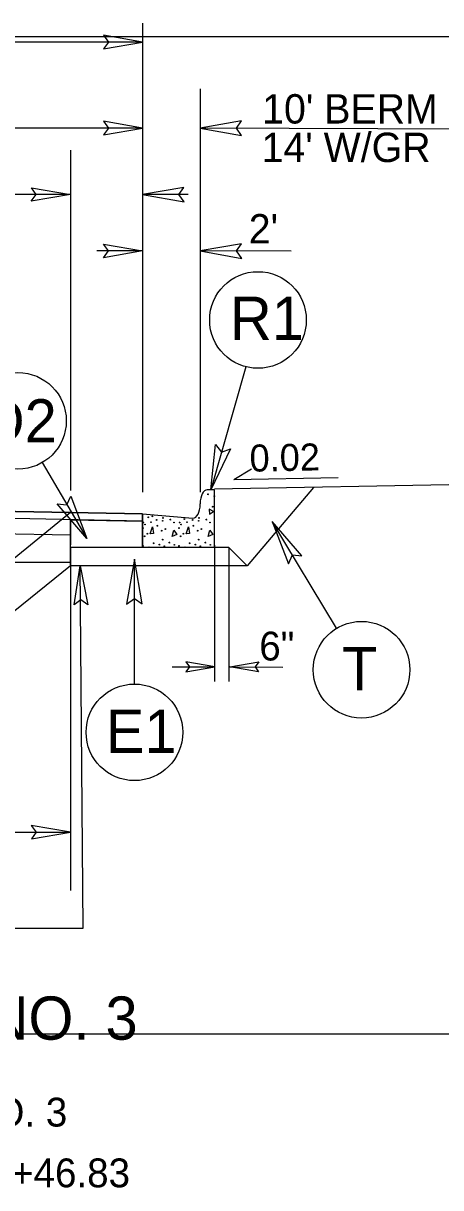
# Model space of a CAD drawing. Extents: x 18938 to 19565, y 6931 to 7973.
# Drawn here: x 19338.35 to 19352.83, y 7710.7 to 7751.1 of the extents above; entities that cross this region are included whole.
import ezdxf

# ---------------------------------------------------------------- set-up
doc = ezdxf.new("R2010")
doc.units = 0
for name, color, linetype in [('Old_Level_11', 7, 'Continuous'), ('Old_Level_3', 7, 'Continuous'), ('Prop Pavement Schedule Description CELL', 7, 'Continuous'), ('Prop Terminator CELL', 7, 'Continuous'), ('Sheet Block Title CELL', 7, 'Continuous'), ('Sheet Cutting Line CELL', 7, 'Continuous'), ('Sheet Data Field CELL', 7, 'Continuous'), ('Sheet Plot Border Inside CELL', 7, 'Continuous'), ('Sheet Sticker Incomplete CELL', 7, 'Continuous'), ('Sheet Typical CELL', 7, 'Continuous'), ('Typical Detail Wedge2 CELL', 7, 'Continuous'), ('Typical Guardrail CELL', 7, 'Continuous'), ('Typical Hinge Slope Arterial CELL', 7, 'Continuous'), ('Typical ID Circle CELL', 7, 'Continuous'), ('Typical Terminator CELL', 7, 'Continuous'), ('Typical Text General CELL', 7, 'Continuous')]:
    doc.layers.add(name, color=color, linetype=linetype)

msp = doc.modelspace()

# ---------------------------------------------------------------- linework, layer by layer
at = {"layer": 'Old_Level_3'}
for p, q in [((19343.507, 7728.771), (19344.983, 7728.771)), ((19345.514, 7728.771), (19347.352, 7728.767))]:
    msp.add_line(p, q, dxfattribs=at)
at = {"layer": 'Prop Pavement Schedule Description CELL'}
for p, q in [((19344.983, 7732.915), (19344.983, 7734.915)), ((19354.484, 7735.112), (19344.986, 7734.934)), ((19348.414, 7734.998), (19346.113, 7732.285)), ((19342.484, 7734.081), (19330.484, 7734.321)), ((19342.484, 7733.831), (19330.484, 7734.071)), ((19342.484, 7734.081), (19342.484, 7732.915)), ((19339.984, 7732.285), (19339.984, 7733.244)), ((19345.483, 7732.915), (19342.484, 7732.915)), ((19346.113, 7732.285), (19345.483, 7732.915)), ((19346.113, 7732.285), (19339.984, 7732.285))]:
    msp.add_line(p, q, dxfattribs=at)
at = {"layer": 'Sheet Block Title CELL'}
for p, q in [((19339.984, 7733.881), (19342.484, 7733.831)), ((19339.984, 7732.915), (19339.984, 7733.881)), ((19342.484, 7733.831), (19342.484, 7732.915)), ((19342.484, 7732.915), (19339.984, 7732.915))]:
    msp.add_line(p, q, dxfattribs=at)
at = {"layer": 'Sheet Cutting Line CELL'}
for q in [(19346.261, 7735.643), (19349.275, 7735.346)]:
    msp.add_line((19345.652, 7735.275), q, dxfattribs=at)
at = {"layer": 'Sheet Data Field CELL'}
for points in [[(19341.134, 7750.214), (19342.484, 7750.447), (19341.126, 7750.687), (19341.299, 7750.447)], [(19341.134, 7747.237), (19342.484, 7747.469), (19341.126, 7747.709), (19341.299, 7747.469)], [(19338.634, 7745.398), (19339.984, 7745.166), (19338.626, 7744.926), (19338.799, 7745.166)], [(19341.134, 7743.438), (19342.484, 7743.205), (19341.126, 7742.965), (19341.299, 7743.205)], [(19340.108, 7730.932), (19340.323, 7732.285), (19340.581, 7730.931), (19340.338, 7731.1)], [(19338.634, 7722.803), (19339.984, 7723.035), (19338.626, 7723.275), (19338.799, 7723.035)]]:
    msp.add_lwpolyline(points, close=True, dxfattribs=at)
at = {"layer": 'Sheet Sticker Incomplete CELL'}
for p, q in [((19344.983, 7734.915), (19344.723, 7734.915)), ((19344.983, 7732.915), (19344.983, 7734.915)), ((19344.484, 7734.414), (19344.484, 7734.436)), ((19342.484, 7732.915), (19342.484, 7734.081)), ((19342.484, 7734.081), (19344.234, 7733.936)), ((19344.793, 7734.248), (19344.81, 7734.067)), ((19344.947, 7734.159), (19344.793, 7734.248)), ((19344.81, 7734.067), (19344.947, 7734.159)), ((19342.744, 7733.394), (19342.831, 7733.634)), ((19342.831, 7733.634), (19342.865, 7733.407)), ((19343.994, 7733.394), (19344.079, 7733.634)), ((19344.079, 7733.634), (19344.114, 7733.407)), ((19342.865, 7733.407), (19342.744, 7733.394)), ((19343.51, 7733.292), (19343.572, 7733.521)), ((19343.675, 7733.371), (19343.51, 7733.292)), ((19343.572, 7733.521), (19343.675, 7733.371)), ((19344.114, 7733.407), (19343.994, 7733.394)), ((19344.758, 7733.292), (19344.821, 7733.521)), ((19344.924, 7733.371), (19344.758, 7733.292)), ((19344.821, 7733.521), (19344.924, 7733.371)), ((19344.983, 7732.915), (19342.484, 7732.915))]:
    msp.add_line(p, q, dxfattribs=at)
for centre, start_param, end_param in [((19344.723, 7734.436), 0, 1.570796), ((19344.244, 7734.414), 3.099976, 4.712389)]:
    msp.add_ellipse(centre, major_axis=(0, 0.479), ratio=0.5, start_param=start_param, end_param=end_param, dxfattribs=at)
for centre in [(19344.753, 7734.763), (19344.97, 7734.695), (19342.825, 7733.998), (19344.919, 7734.329), (19342.5, 7733.589), (19342.517, 7733.783), (19342.573, 7733.715), (19342.682, 7733.964), (19342.779, 7733.794), (19342.973, 7733.873), (19343.002, 7733.669), (19343.179, 7733.84), (19343.196, 7733.941), (19343.453, 7733.884), (19343.573, 7733.783), (19343.749, 7733.589), (19343.767, 7733.783), (19343.823, 7733.715), (19343.931, 7733.902), (19344.028, 7733.794), (19344.222, 7733.873), (19344.251, 7733.669), (19344.428, 7733.84), (19344.445, 7733.941), (19344.702, 7733.884), (19344.822, 7733.783), (19342.557, 7733.304), (19342.654, 7733.395), (19343.15, 7733.498), (19343.184, 7733.19), (19343.276, 7733.555), (19343.806, 7733.304), (19343.903, 7733.395), (19344.399, 7733.498), (19344.433, 7733.19), (19344.525, 7733.555), (19342.495, 7732.972), (19342.705, 7732.927), (19342.865, 7733.064), (19343.07, 7733.018), (19343.241, 7732.961), (19343.418, 7733.087), (19343.59, 7733.007), (19343.744, 7732.972), (19343.954, 7732.927), (19344.114, 7733.064), (19344.319, 7733.018), (19344.491, 7732.961), (19344.667, 7733.087), (19344.839, 7733.007)]:
    msp.add_ellipse(centre, major_axis=(0, 0.016), ratio=0.5, dxfattribs=at)
at = {"layer": 'Sheet Typical CELL'}
for p, q in [((19342.484, 7751.103), (19342.484, 7734.841)), ((19342.484, 7750.447), (19318.484, 7750.447)), ((19344.484, 7748.83), (19344.484, 7734.841)), ((19342.484, 7747.469), (19330.484, 7747.469)), ((19354.484, 7747.422), (19344.482, 7747.468)), ((19339.984, 7746.703), (19339.984, 7734.891)), ((19339.984, 7745.166), (19336.204, 7745.166)), ((19344.063, 7745.161), (19342.484, 7745.163)), ((19342.484, 7743.205), (19340.904, 7743.205)), ((19347.643, 7743.199), (19344.484, 7743.203)), ((19339.984, 7734.131), (19335.929, 7730.847)), ((19339.984, 7732.91), (19339.984, 7721.02)), ((19344.983, 7732.995), (19344.983, 7728.264)), ((19345.483, 7732.894), (19345.483, 7728.264)), ((19339.984, 7732.285), (19335.879, 7728.96)), ((19340.423, 7719.705), (19340.323, 7732.285)), ((19320.984, 7723.035), (19339.984, 7723.035)), ((19320.544, 7719.705), (19340.423, 7719.705))]:
    msp.add_line(p, q, dxfattribs=at)
at = {"layer": 'Typical Guardrail CELL'}
for p, q in [((19233.04, 7750.645), (19380.142, 7750.645)), ((19221.092, 7716.037), (19380.142, 7716.037))]:
    msp.add_line(p, q, dxfattribs=at)
at = {"layer": 'Typical Hinge Slope Arterial CELL'}
for p, q in [((19330.484, 7734.321), (19342.484, 7734.081)), ((19342.484, 7733.831), (19330.484, 7734.071)), ((19342.484, 7734.081), (19342.484, 7733.831))]:
    msp.add_line(p, q, dxfattribs=at)
at = {"layer": 'Typical ID Circle CELL'}
for p, q in [((19339.984, 7733.881), (19339.984, 7733.009)), ((19330.484, 7733.532), (19339.984, 7733.354)), ((19339.984, 7732.4), (19320.984, 7732.4))]:
    msp.add_line(p, q, dxfattribs=at)
at = {"layer": 'Typical Terminator CELL'}
for p, q in [((19346.069, 7739.187), (19344.853, 7734.915)), ((19339.007, 7735.863), (19340.55, 7733.225)), ((19349.217, 7730.112), (19346.984, 7733.823)), ((19342.204, 7728.178), (19342.204, 7732.509))]:
    msp.add_line(p, q, dxfattribs=at)
for centre in [(19346.489, 7740.809), (19338.162, 7737.31), (19350.081, 7728.676), (19342.204, 7726.503)]:
    msp.add_circle(centre, 1.676, dxfattribs=at)
at = {"layer": 'Typical Text General CELL'}
for points in [[(19345.914, 7747.715), (19344.482, 7747.468), (19345.922, 7747.214), (19345.739, 7747.468)], [(19343.916, 7745.41), (19342.484, 7745.163), (19343.924, 7744.909), (19343.741, 7745.163)], [(19345.916, 7743.449), (19344.484, 7743.203), (19345.924, 7742.948), (19345.741, 7743.203)], [(19345.535, 7736.334), (19344.853, 7734.915), (19345.015, 7736.491), (19345.226, 7736.225)], [(19339.997, 7734.699), (19340.55, 7733.225), (19339.524, 7734.433), (19339.862, 7734.401)], [(19348.013, 7732.631), (19346.984, 7733.823), (19347.552, 7732.344), (19347.686, 7732.656)], [(19342.471, 7730.958), (19342.204, 7732.509), (19341.928, 7730.949), (19342.204, 7731.147)], [(19343.991, 7728.598), (19344.989, 7728.77), (19343.986, 7728.947), (19344.113, 7728.77)], [(19346.511, 7728.599), (19345.514, 7728.771), (19346.517, 7728.948), (19346.39, 7728.771)]]:
    msp.add_lwpolyline(points, close=True, dxfattribs=at)

# ---------------------------------------------------------------- texts
at = {"layer": 'Old_Level_11'}
for s, height, p in [('TYPICAL SECTION NO. 3', 1.5, (19318.686, 7715.839)), ('USE TYPICAL SECTION NO. 3', 1, (19320.999, 7712.826))]:
    msp.add_text(s, height=height, dxfattribs=at).set_placement(p)
at = {"layer": 'Old_Level_3'}
for s, height, p in [("10' BERM", 1.0188, (19346.634, 7747.625)), ("14' W/GR", 1.0188, (19346.614, 7746.289)), ("2'", 1.0188, (19346.169, 7743.464)), ('6"', 1, (19346.534, 7728.995))]:
    msp.add_text(s, height=height, dxfattribs=at).set_placement(p)
at = {"layer": 'Prop Terminator CELL'}
for s, rotation, p in [('R1', 360, (19345.519, 7740.12)), ('T', 359.9996, (19349.409, 7727.965)), ('E1', 360, (19341.212, 7725.791))]:
    msp.add_text(s, height=1.5, rotation=rotation, dxfattribs=at).set_placement(p)
msp.add_text('D2', height=1.5, dxfattribs=at).set_placement((19336.945, 7736.56))
at = {"layer": 'Sheet Plot Border Inside CELL'}
msp.add_text('0.02', height=0.9375, rotation=1.1199, dxfattribs=at).set_placement((19346.206, 7735.545))
at = {"layer": 'Typical Detail Wedge2 CELL'}
msp.add_text('-L- STA. 197+50.85 TO STA. 209+46.83', height=1, dxfattribs=at).set_placement((19318.04, 7710.718))

doc.saveas('drawing.dxf')
